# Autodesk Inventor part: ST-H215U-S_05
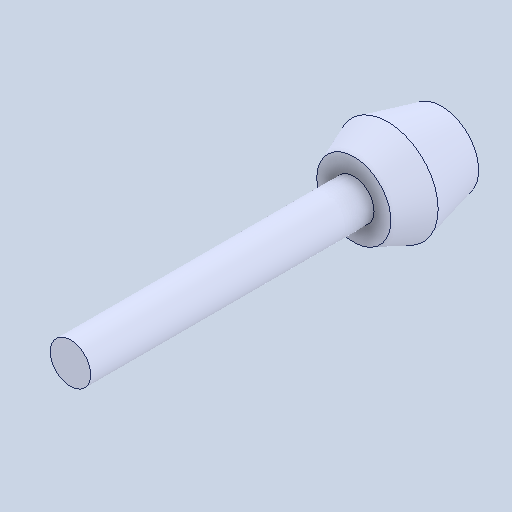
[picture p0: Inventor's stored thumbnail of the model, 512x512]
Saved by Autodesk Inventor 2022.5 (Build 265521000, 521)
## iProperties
Created: 2024-07
Part Number: ST-H215U-S_05
Material: 一般
Document SubType Name: Modeling
Designer: ImaoCorp
Density: 1 g/cm^3
Appearance: 既定
Author: ImaoCorp
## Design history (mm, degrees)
feature "ST-H215U-S_05"
node "ソリッド1"
